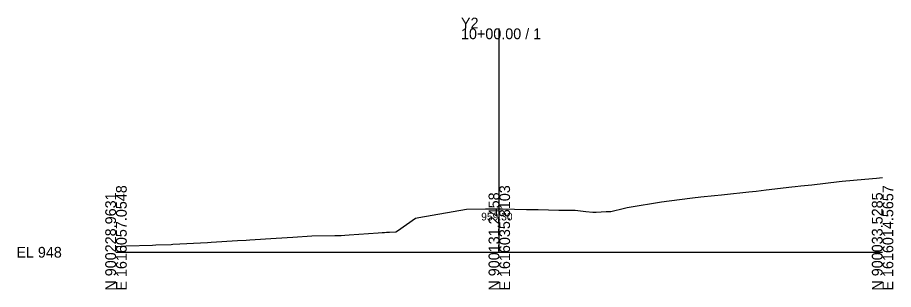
# Model space of a CAD drawing. Extents: x -26 to 1403, y -10 to 2517.
# Drawn here: x -25.7 to 202.8, y -9.7 to 61.2 of the extents above; entities that cross this region are included whole.
import ezdxf

# ---------------------------------------------------------------- set-up
doc = ezdxf.new("R2010")
doc.units = 0
for name, color, linetype in [('Exist Cross Section Cell', 7, 'Continuous'), ('Exist XS Center Line Elevation Label', 7, 'Continuous'), ('Exist XS Ground Line', 7, 'Continuous')]:
    doc.layers.add(name, color=color, linetype=linetype)

msp = doc.modelspace()

# ---------------------------------------------------------------- linework, layer by layer
at = {"layer": 'Exist Cross Section Cell'}
for p, q in [((100, 0), (100, 58.35)), ((0, 0), (100, 0)), ((100, 0), (200, 0))]:
    msp.add_line(p, q, dxfattribs=at)
at = {"layer": 'Exist XS Ground Line'}
for p, q in [((181.56, 17.56), (188.7, 18.44)), ((188.7, 18.44), (189.46, 18.51)), ((189.46, 18.51), (195.35, 19.08)), ((195.35, 19.08), (198.44, 19.34)), ((198.44, 19.34), (200, 19.45)), ((166.98, 15.97), (169.63, 16.28)), ((169.63, 16.28), (176.28, 17.06)), ((176.28, 17.06), (177.21, 17.14)), ((177.21, 17.14), (178.63, 17.3)), ((178.63, 17.3), (181.56, 17.56)), ((142.36, 13.12), (147.02, 13.75)), ((147.02, 13.75), (150.42, 14.23)), ((150.42, 14.23), (152.58, 14.46)), ((152.58, 14.46), (156.17, 14.84)), ((156.17, 14.84), (157.98, 15)), ((157.98, 15), (158.74, 15.09)), ((158.74, 15.09), (165.06, 15.75)), ((165.06, 15.75), (166.98, 15.97)), ((129.09, 10.6), (132.67, 11.46)), ((132.67, 11.46), (133.38, 11.66)), ((133.38, 11.66), (133.87, 11.73)), ((133.87, 11.73), (142.36, 13.12)), ((79.05, 9.06), (91.48, 11.26)), ((91.48, 11.26), (96.4, 11.3)), ((96.4, 11.3), (100, 11.3)), ((100, 11.3), (100.8, 11.29)), ((100.8, 11.29), (107.08, 11.18)), ((107.08, 11.18), (108.39, 11.12)), ((108.39, 11.12), (110.18, 11.11)), ((110.18, 11.11), (115.53, 10.95)), ((115.53, 10.95), (118.07, 11)), ((118.07, 11), (119.23, 10.99)), ((119.23, 10.99), (119.79, 10.99)), ((119.79, 10.99), (122.58, 10.62)), ((122.58, 10.62), (124.44, 10.43)), ((124.44, 10.43), (125.31, 10.49)), ((125.31, 10.49), (127.92, 10.61)), ((127.92, 10.61), (129.09, 10.6)), ((73.42, 5.6), (78.18, 8.93)), ((78.18, 8.93), (79.05, 9.06)), ((60.83, 4.52), (68.43, 5.1)), ((68.43, 5.1), (69.48, 5.14)), ((69.48, 5.14), (70.03, 5.18)), ((70.03, 5.18), (70.57, 5.22)), ((70.57, 5.22), (71.38, 5.27)), ((71.38, 5.27), (72.98, 5.35)), ((72.98, 5.35), (73.42, 5.6)), ((14.87, 2.11), (23.89, 2.53)), ((23.89, 2.53), (24.87, 2.6)), ((24.87, 2.6), (31.67, 3.03)), ((31.67, 3.03), (34, 3.19)), ((34, 3.19), (34.91, 3.26)), ((34.91, 3.26), (41.81, 3.69)), ((41.81, 3.69), (46.14, 3.98)), ((46.14, 3.98), (51.11, 4.29)), ((51.11, 4.29), (57.13, 4.39)), ((57.13, 4.39), (58.75, 4.41)), ((58.75, 4.41), (59.69, 4.48)), ((59.69, 4.48), (60.83, 4.52)), ((0, 1.5), (2.66, 1.65)), ((2.66, 1.65), (9.48, 1.88)), ((9.48, 1.88), (10.36, 1.9)), ((10.36, 1.9), (14.43, 2.07)), ((14.43, 2.07), (14.87, 2.11))]:
    msp.add_line(p, q, dxfattribs=at)

# ---------------------------------------------------------------- texts
at = {"layer": 'Exist Cross Section Cell'}
for s, p in [('Y2', (90, 58.35)), ('10+00.00 / 1', (90, 55.55)), ('EL 948', (-26, -1.4))]:
    msp.add_text(s, height=2.8, dxfattribs=at).set_placement(p)
for s, p in [('E 1616057.0548', (2.8, -10)), ('E 1616035.8103', (102.8, -10)), ('E 1616014.5657', (202.8, -10)), ('N 900228.9631', (0, -10)), ('N 900131.2458', (100, -10)), ('N 900033.5285', (200, -10))]:
    msp.add_text(s, height=2.8, rotation=90, dxfattribs=at).set_placement(p)
at = {"layer": 'Exist XS Center Line Elevation Label'}
msp.add_text('959.30', height=2, dxfattribs=at).set_placement((95.28, 8.3))

doc.saveas('drawing.dxf')
